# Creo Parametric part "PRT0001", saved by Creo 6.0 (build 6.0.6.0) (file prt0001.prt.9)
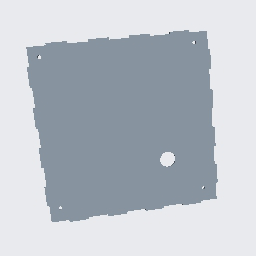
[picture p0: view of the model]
Units: Inch lbm Second (Pro/E Default); INCH, POUND, SECS

Created from: INLBS_PART_SOLID.PRT

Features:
  1. datum plane "RIGHT"
  2. datum plane "TOP"
  3. datum plane "FRONT"
  4. coordinate system
  5. sketch "Sketch 1"
  6. extrusion "Extrude 1"
  7. sketch "Sketch 2"
  8. extruded cut "Extrude 2"
  9. sketch "Sketch 3"
  10. extruded cut "Extrude 3"
  11. sketch "Sketch 4"
  12. extruded cut "Extrude 4"

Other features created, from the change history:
  extrusion "Extrude 2" (2 times)
  mirror "Mirror 1"

Surfaces: 70 plane, 5 cylinder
